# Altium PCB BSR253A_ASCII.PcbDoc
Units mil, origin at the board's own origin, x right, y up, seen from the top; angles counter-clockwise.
Board outline 1000 x 800 mil, 4 copper layers (Top Layer, Signal Layer 1, Signal Layer 2, Bottom Layer), stack 60.6 mil thick; 27 components, 15 nets, 56 pads, 23 vias.
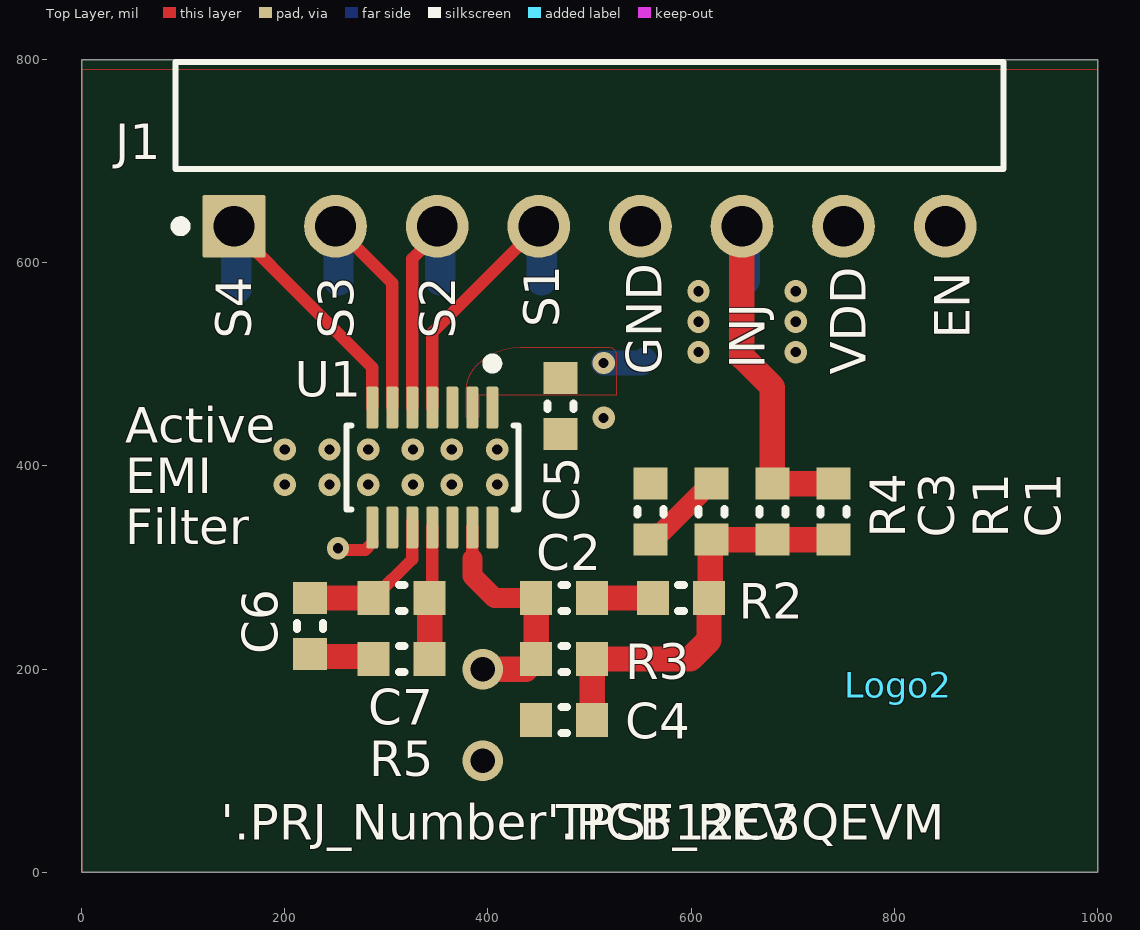
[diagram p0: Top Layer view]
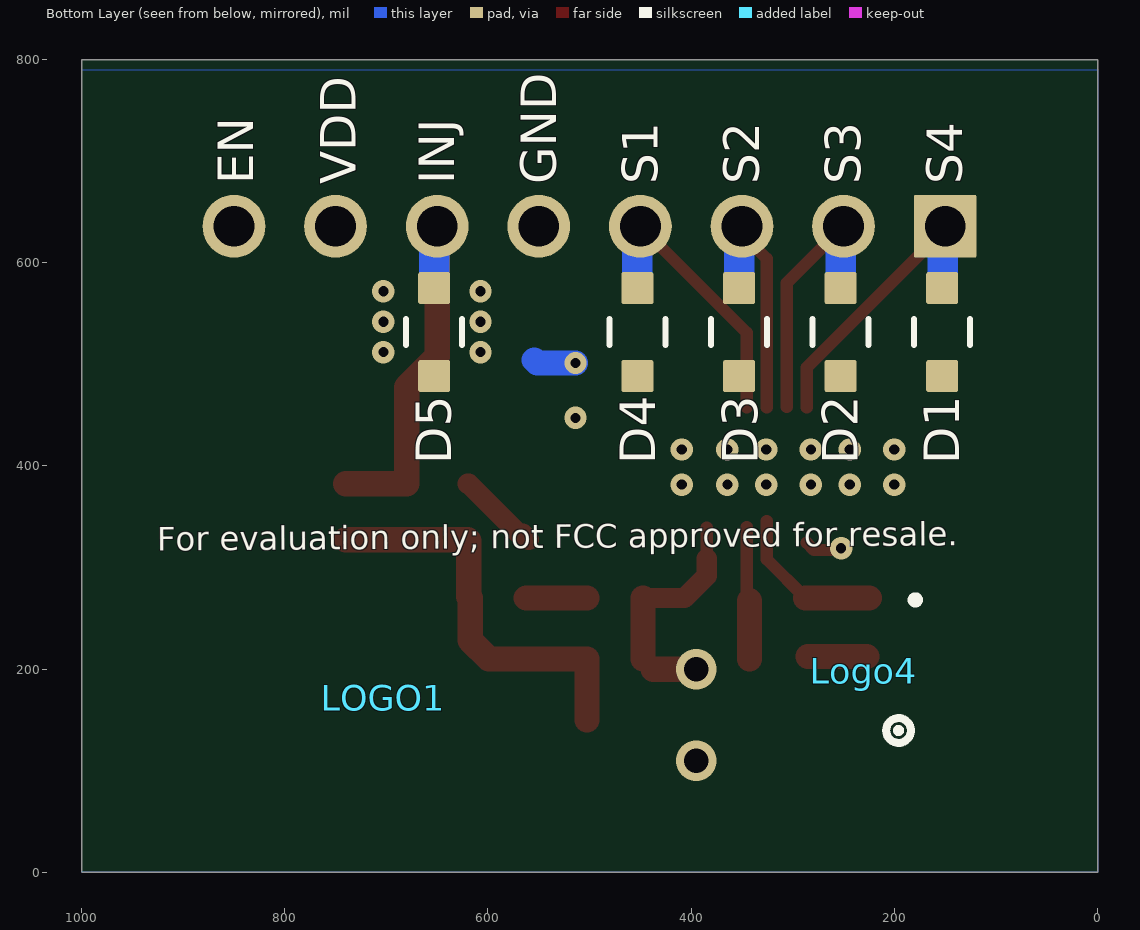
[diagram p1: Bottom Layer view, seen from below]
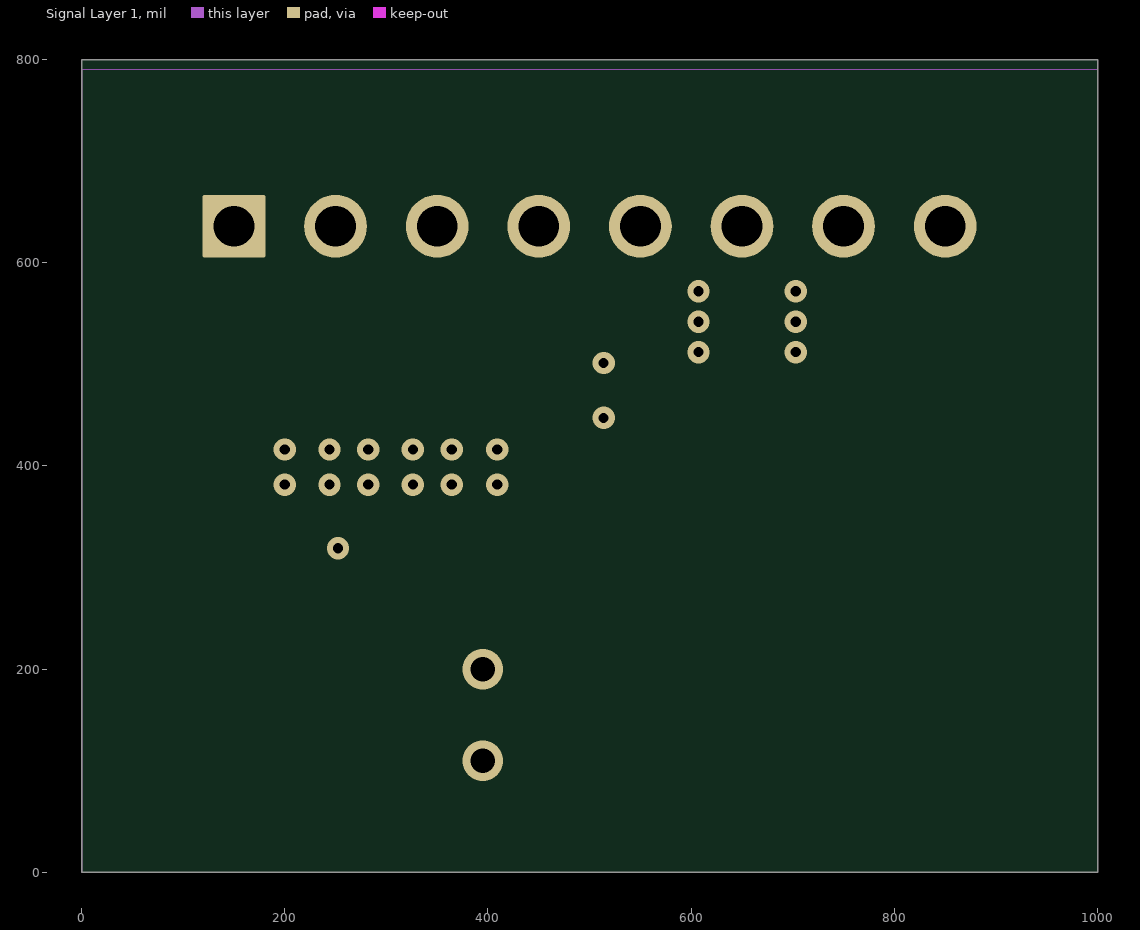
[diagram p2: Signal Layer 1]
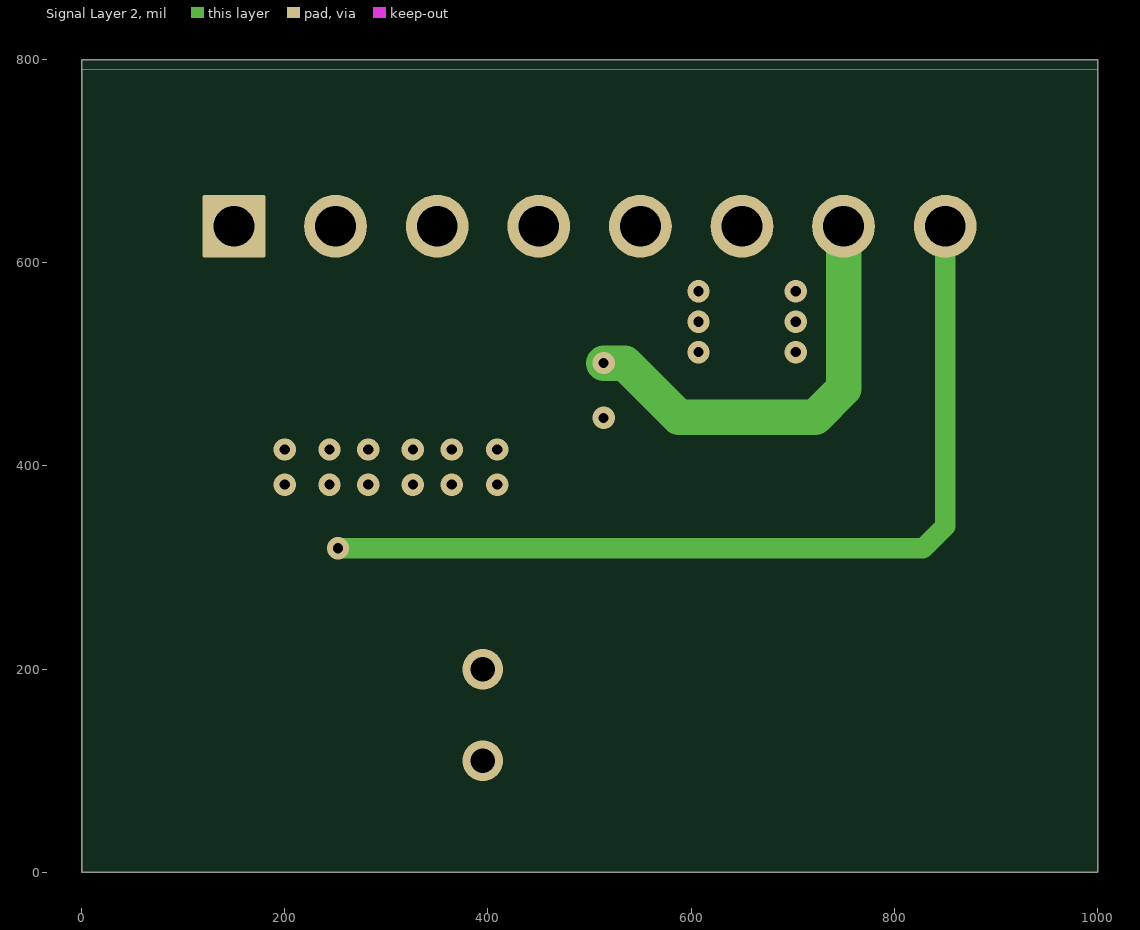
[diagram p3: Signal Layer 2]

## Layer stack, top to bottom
Top Solder: solder mask 0.4, Solder Resist, Dk 3.5
Top Layer: signal copper 1.4
Dielectric 1: prepreg 7, FR-4 High Tg, Dk 4.2
Signal Layer 1: signal copper 1.4
Dielectric 2: core 41, FR-4 High Tg, Dk 4.2
Signal Layer 2: signal copper 1.4
Dielectric 3: prepreg 7, FR-4 High Tg, Dk 4.2
Bottom Layer: signal copper 1.4
Bottom Solder: solder mask 0.4, Solder Resist, Dk 3.5

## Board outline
0,0 1000,0 1000,800 0,800

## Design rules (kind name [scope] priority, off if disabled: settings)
AcuteAngle [All] p0: scope1count=1 scope1_0_kind=Board scope1_0_value=Board scope2count=1 scope2_0_kind=Board scope2_0_value=Board commentlength=0 minimum=4.50000000000000E+0001
AcuteAngle [All] p1: minimum=4.50000000000000E+0001 checktracksonly=FALSE
AssemblyTestPointUsage [All] p0: scope1count=1 scope1_0_kind=Board scope1_0_value=Board scope2count=1 scope2_0_kind=Board scope2_0_value=Board commentlength=0
AssemblyTestPointUsage [All] p1: valid=2
AssemblyTestpoint [All] p0: scope1count=1 scope1_0_kind=Board scope1_0_value=Board scope2count=1 scope2_0_kind=Board scope2_0_value=Board commentlength=0
AssemblyTestpoint [All] p1: testpointundercomponent=FALSE minsize=32 maxsize=100 preferedsize=60 minholesize=0 maxholesize=40 preferedholesize=32 testpointgrid=1 usegrid=TRUE gridtolerance=0.01 allowsidetop=TRUE allowsidebottom=TRUE
BoardOutlineClearance BoardOutlineClearance_MountingHoles [All] p0 off: scope1count=1 scope1_0_kind=Board scope1_0_value=Board scope2count=1 scope2_0_kind=Board scope2_0_value=Board commentlength=86 gap=30 // Protel DXP Scope 1 Expression Was: OnCopper and InComponentClass('Mounting Holes')
BoardOutlineClearance BoardOutlineClearance_Poly [All] p0 off: scope1count=1 scope1_0_kind=Board scope1_0_value=Board scope2count=1 scope2_0_kind=Board scope2_0_value=Board commentlength=58 gap=25 // Protel DXP Scope 1 Expression Was: OnCopper and IsPoly
BoardOutlineClearance [All] p0 off: scope1count=1 scope1_0_kind=Board scope1_0_value=Board scope2count=1 scope2_0_kind=Board scope2_0_value=Board commentlength=172 gap=30 // Protel DXP Scope 1 Expression Was: OnCopper and Not InComponentClass('Logo') and not InComponentClass('FiducialMark') and not InRegion(1000,500,4000,800) and not InPoly
BoardOutlineClearance BoardOutlineClearance_MountingHoles [OnCopper and InComponentClass('Mounting Holes')] p1: gap=30 ignorepadtopadclearanceinfootprint=FALSE
BoardOutlineClearance BoardOutlineClearance_Poly [OnCopper and IsPoly] p2: gap=25 ignorepadtopadclearanceinfootprint=FALSE
BoardOutlineClearance [OnCopper and Not InComponentClass('Logo') and not InComponentClass('FiducialMark') and not InRegion(1000,500,4000,800) and not InPoly] p3: gap=30 ignorepadtopadclearanceinfootprint=FALSE
Clearance Clearance_Poly [All] p0 off: scope1count=1 scope1_0_kind=Board scope1_0_value=Board scope2count=1 scope2_0_kind=Board scope2_0_value=Board commentlength=48 gap=10 // Protel DXP Scope 1 Expression Was: InPolygon
Clearance Clearance_FiducialMark [All] p0 off: scope1count=1 scope1_0_kind=Board scope1_0_value=Board scope2count=1 scope2_0_kind=Board scope2_0_value=Board commentlength=84 gap=0 // Protel DXP Scope 2 Expression Was: IsSMTPin and InComponentClass('FiducialMark')
Clearance [All] p0: scope1count=1 scope1_0_kind=Board scope1_0_value=Board scope2count=1 scope2_0_kind=Board scope2_0_value=Board commentlength=0 gap=6
Clearance Clearance_TopLayer [All] p0: scope1count=1 scope1_0_kind=Layer scope1_0_value=TOP scope2count=1 scope2_0_kind=Layer scope2_0_value=TOP commentlength=0 gap=6
Clearance Clearance_FiducialMark [IsKeepOut and InComponentClass('FiducialMark') vs IsSMTPin and InComponentClass('FiducialMark')] p1: gap=0 ignorepadtopadclearanceinfootprint=TRUE
Clearance Clearance_TopLayer [OnLayer('Top Layer') vs OnLayer('Top Layer')] p2: gap=6 ignorepadtopadclearanceinfootprint=FALSE
Clearance Clearance_Poly [InPolygon] p3: gap=10 ignorepadtopadclearanceinfootprint=FALSE
Clearance [All] p4: gap=6 ignorepadtopadclearanceinfootprint=FALSE
ComponentClearance ComponentClearance_MountingHoles_FiducialMarks [All] p0: scope1count=1 scope1_0_kind=ComponentClass scope1_0_value="Mounting Holes" scope2count=1 scope2_0_kind=ComponentClass scope2_0_value=FiducialMark commentlength=0 gap=50 collisioncheckmode=3
ComponentClearance ComponentClearance_Shunt [All] p0: scope1count=1 scope1_0_kind=ComponentClass scope1_0_value=Header scope2count=1 scope2_0_kind=ComponentClass scope2_0_value=Shunt commentlength=0 gap=0 collisioncheckmode=3
ComponentClearance ComponentClearance_Logo [All] p0: scope1count=1 scope1_0_kind=ComponentClass scope1_0_value=Logo scope2count=1 scope2_0_kind=Board scope2_0_value=Board commentlength=0 gap=0 collisioncheckmode=3
ComponentClearance ComponentClearance_ScrewToNut [All] p0 off: scope1count=1 scope1_0_kind=Board scope1_0_value=Board scope2count=1 scope2_0_kind=Board scope2_0_value=Board commentlength=71 gap=5 collisioncheckmode=3 // Protel DXP Scope 2 Expression Was: (HasFootprint('Keystone_1902C'))
ComponentClearance ComponentClearance_MountingHoles [All] p0: scope1count=1 scope1_0_kind=ComponentClass scope1_0_value="Mounting Holes" scope2count=1 scope2_0_kind=Board scope2_0_value=Board commentlength=0 gap=250 collisioncheckmode=3
ComponentClearance ComponentClearance_SmallPassives [All] p0 off: scope1count=1 scope1_0_kind=Board scope1_0_value=Board scope2count=1 scope2_0_kind=Board scope2_0_value=Board commentlength=508 gap=14.96 collisioncheckmode=3 // Protel DXP Scope 2 Expression Was: HasFootprint('0201*') or HasFootprint('0402*') or HasFootprint('0508') or HasFootprint('0603*') or HasFootprint('0612') or HasFootprint('0805*') or HasFootprint('0815*') or HasFootprint('0830*') or HasFootprint('1206*') or HasFootprint('1210*') or HasFootprint('1808*') or HasFootprint('1812*') or HasFootprint('1825*') or HasFootprint('2010*') or HasFootprint('2220*') or HasFootprint('2225*') or HasFootprint('2512*') or HasFootprint('2728*') or HasFootprint('3518*')
ComponentClearance ComponentClearance_THtoSMT [All] p0 off: scope1count=1 scope1_0_kind=Board scope1_0_value=Board scope2count=1 scope2_0_kind=Board scope2_0_value=Board commentlength=53 gap=19.68 collisioncheckmode=3 // Protel DXP Scope 2 Expression Was: IsSMTComponent
ComponentClearance ComponentClearance_THtoTH [All] p0 off: scope1count=1 scope1_0_kind=Board scope1_0_value=Board scope2count=1 scope2_0_kind=Board scope2_0_value=Board commentlength=54 gap=30 collisioncheckmode=3 // Protel DXP Scope 2 Expression Was: IsThruComponent
ComponentClearance ComponentClearance_MountingHoles_FiducialMarks [InComponentClass('Mounting Holes') vs InComponentClass('FiducialMark')] p1: gap=50 collisioncheckmode=3 verticalgap=10 showdistances=FALSE
ComponentClearance ComponentClearance_Shunt [InComponentClass('Header') vs InComponentClass('Shunt')] p2: gap=0 collisioncheckmode=3 verticalgap=0 showdistances=FALSE
ComponentClearance ComponentClearance_Logo [InComponentClass('Logo')] p3: gap=0 collisioncheckmode=3 verticalgap=0 showdistances=FALSE
ComponentClearance ComponentClearance_ScrewToNut [(HasFootprint('NY PMS 440 0025 PH')) vs (HasFootprint('Keystone_1902C'))] p4: gap=5 collisioncheckmode=3 verticalgap=10 showdistances=FALSE
ComponentClearance ComponentClearance_MountingHoles [InComponentClass('Mounting Holes')] p5: gap=250 collisioncheckmode=3 verticalgap=100000 showdistances=FALSE
ComponentClearance ComponentClearance_SmallPassives [HasFootprint('0201*') or HasFootprint('0402*') or HasFootprint('0508') or HasFootprint('0603*') or HasFootprint('0612') or HasFootprint('0805*') or HasFootprint('0815*') or HasFootprint('0830*') or HasFootprint('1206*') or HasFootprint('1210*') or HasFootprint('1808*') or HasFootprint('1812*') or HasFootprint('1825*') or HasFootprint('2010*') or HasFootprint('2220*') or HasFootprint('2225*') or HasFootprint('2512*') or HasFootprint('2728*') or HasFootprint('3518*') vs HasFootprint('0201*') or HasFootprint('0402*') or HasFootprint('0508') or HasFootprint('0603*') or HasFootprint('0612') or HasFootprint('0805*') or HasFootprint('0815*') or HasFootprint('0830*') or HasFootprint('1206*') or HasFootprint('1210*') or HasFootprint('1808*') or HasFootprint('1812*') or HasFootprint('1825*') or HasFootprint('2010*') or HasFootprint('2220*') or HasFootprint('2225*') or HasFootprint('2512*') or HasFootprint('2728*') or HasFootprint('3518*')] p6: gap=14.96 collisioncheckmode=3 verticalgap=10 showdistances=FALSE
ComponentClearance ComponentClearance_THtoSMT [IsThruComponent vs IsSMTComponent] p7: gap=19.68 collisioncheckmode=3 verticalgap=30 showdistances=FALSE
ComponentClearance ComponentClearance_THtoTH [IsThruComponent vs IsThruComponent] p8: gap=30 collisioncheckmode=3 verticalgap=30 showdistances=FALSE
DiffPairsRouting [All] p0: scope1count=1 scope1_0_kind=Board scope1_0_value=Board scope2count=1 scope2_0_kind=Board scope2_0_value=Board commentlength=0
DiffPairsRouting [All] p1: maxlimit=100 minlimit=10 mostfreqgap=10 toplayer_minwidth=15 toplayer_maxwidth=15 toplayer_prefwidth=15 midlayer1_minwidth=15 midlayer1_maxwidth=15 midlayer1_prefwidth=15 midlayer2_minwidth=15 midlayer2_maxwidth=15 midlayer2_prefwidth=15 bottomlayer_minwidth=15 bottomlayer_maxwidth=15 bottomlayer_prefwidth=15 maxuncoupledlength=1000
FabricationTestPointUsage TestPointUsage [All] p0: scope1count=1 scope1_0_kind=Board scope1_0_value=Board scope2count=1 scope2_0_kind=Board scope2_0_value=Board commentlength=0 valid=2 allowmultiple=FALSE
FabricationTestPointUsage TestPointUsage [All] p1: valid=2 allowmultiple=FALSE
FabricationTestpoint Testpoint [All] p0: scope1count=1 scope1_0_kind=Board scope1_0_value=Board scope2count=1 scope2_0_kind=Board scope2_0_value=Board commentlength=0 side=3 testpointundercomponent=TRUE minsize=32 maxsize=100 preferedsize=60 minholesize=0 maxholesize=40 preferedholesize=32 testpointgrid=1
FabricationTestpoint Testpoint [All] p1: side=3 testpointundercomponent=TRUE minsize=32 maxsize=100 preferedsize=60 minholesize=0 maxholesize=40 preferedholesize=32 testpointgrid=1 allowsidetop=TRUE allowsidebottom=TRUE usegrid=TRUE gridtolerance=0.01
FanoutControl Fanout_LCC [All] p0 off: scope1count=1 scope1_0_kind=Board scope1_0_value=Board scope2count=1 scope2_0_kind=Board scope2_0_value=Board commentlength=69 // Protel DXP Scope 1 Expression Was: IsLCC   Fanout_LCC (Default Rule)
FanoutControl Fanout_BGA [All] p0 off: scope1count=1 scope1_0_kind=Board scope1_0_value=Board scope2count=1 scope2_0_kind=Board scope2_0_value=Board commentlength=69 // Protel DXP Scope 1 Expression Was: IsBGA   Fanout_BGA (Default Rule)
FanoutControl Fanout_SOIC [All] p0 off: scope1count=1 scope1_0_kind=Board scope1_0_value=Board scope2count=1 scope2_0_kind=Board scope2_0_value=Board commentlength=71 // Protel DXP Scope 1 Expression Was: IsSOIC   Fanout_SOIC (Default Rule)
FanoutControl Fanout_Default [All] p0: scope1count=1 scope1_0_kind=Board scope1_0_value=Board scope2count=1 scope2_0_kind=Board scope2_0_value=Board commentlength=30 // Fanout_Default (Default Rule)
FanoutControl Fanout_Small [All] p0 off: scope1count=1 scope1_0_kind=Board scope1_0_value=Board scope2count=1 scope2_0_kind=Board scope2_0_value=Board commentlength=84 // Protel DXP Scope 1 Expression Was: (CompPinCount < 5)   Fanout_Small (Default Rule)
FanoutControl Fanout_LCC [IsLCC] p1: bgadir=Out bgaviamode=Centered fanoutstyle=Auto fanoutdirection=Alternating viagrid=1 // Fanout_LCC (Default Rule)
FanoutControl Fanout_BGA [IsBGA] p2: bgadir=Out bgaviamode=Centered fanoutstyle=Auto fanoutdirection=Alternating viagrid=1 // Fanout_BGA (Default Rule)
FanoutControl Fanout_Default [All] p4: bgadir=Out bgaviamode=Centered fanoutstyle=Auto fanoutdirection=Alternating viagrid=1 // Fanout_Default (Default Rule)
FanoutControl Fanout_Small [(CompPinCount < 5)] p5: bgadir=Out bgaviamode=Centered fanoutstyle=Auto fanoutdirection=OutThenIn viagrid=1 // Fanout_Small (Default Rule)
Height [All] p0: scope1count=1 scope1_0_kind=Board scope1_0_value=Board scope2count=1 scope2_0_kind=Board scope2_0_value=Board commentlength=0
HoleSize [All] p0: scope1count=1 scope1_0_kind=Board scope1_0_value=Board scope2count=1 scope2_0_kind=Board scope2_0_value=Board commentlength=0 absolutevalues=TRUE maxlimit=251 minlimit=7.87 maxpercent=80.000 minpercent=20.000
HoleSize [All] p1: absolutevalues=TRUE maxlimit=251 minlimit=7.87 maxpercent=80.000 minpercent=20.000
HoleToHoleClearance [All] p0: scope1count=1 scope1_0_kind=Board scope1_0_value=Board scope2count=1 scope2_0_kind=Board scope2_0_value=Board commentlength=0
LayerPairs [All] p0: scope1count=1 scope1_0_kind=Board scope1_0_value=Board scope2count=1 scope2_0_kind=Board scope2_0_value=Board commentlength=0 enforce=TRUE
MinimumAnnularRing MinimumAnnularRing_ThermalPadVias [All] p0 off: scope1count=1 scope1_0_kind=Board scope1_0_value=Board scope2count=1 scope2_0_kind=Board scope2_0_value=Board commentlength=63 minimumring=5.91 // Protel DXP Scope 1 Expression Was: IsVia and InAnyComponent
MinimumAnnularRing [All] p0: scope1count=1 scope1_0_kind=Board scope1_0_value=Board scope2count=1 scope2_0_kind=Board scope2_0_value=Board commentlength=0 minimumring=6
MinimumAnnularRing MinimumAnnularRing_ThermalPadVias [IsVia and InAnyComponent] p1: minimumring=5.91
MinimumAnnularRing [All] p2: minimumring=6
MinimumSolderMaskSliver MinimumSolderMaskSliver_Logo [All] p0: scope1count=1 scope1_0_kind=ComponentClass scope1_0_value=Logo scope2count=1 scope2_0_kind=ComponentClass scope2_0_value=Logo commentlength=0
MinimumSolderMaskSliver [All] p0: scope1count=1 scope1_0_kind=Board scope1_0_value=Board scope2count=1 scope2_0_kind=Board scope2_0_value=Board commentlength=0
MinimumSolderMaskSliver MinimumSolderMaskSliver_Logo [InComponentClass('Logo') vs InComponentClass('Logo')] p1: minsoldermaskwidth=0.7
MinimumSolderMaskSliver [All] p2: minsoldermaskwidth=3.94
NetAntennae [All] p0: scope1count=1 scope1_0_kind=Layer scope1_0_value=TOP scope2count=1 scope2_0_kind=Board scope2_0_value=Board commentlength=0
NetAntennae [OnLayer('Top Layer')] p1: netantennaetolerance=0
PasteMaskExpansion [All] p0: scope1count=1 scope1_0_kind=Board scope1_0_value=Board scope2count=1 scope2_0_kind=Board scope2_0_value=Board commentlength=0 expansion=0
PlaneClearance [All] p0: scope1count=1 scope1_0_kind=Board scope1_0_value=Board scope2count=1 scope2_0_kind=Board scope2_0_value=Board commentlength=0 clearance=20
PlaneConnect [All] p0: scope1count=1 scope1_0_kind=Board scope1_0_value=Board scope2count=1 scope2_0_kind=Board scope2_0_value=Board commentlength=0 planeconnectstyle=Direct reliefexpansion=10 reliefentries=4 reliefconductorwidth=10 reliefairgap=10
PlaneConnect [All] p1: planeconnectstyle=Direct reliefexpansion=10 reliefentries=4 reliefconductorwidth=10 reliefairgap=10
PolygonConnect [All] p0: scope1count=1 scope1_0_kind=Board scope1_0_value=Board scope2count=1 scope2_0_kind=Board scope2_0_value=Board commentlength=0 connectstyle=Direct reliefconductorwidth=10 reliefentries=4 polygonreliefangle="90 Angle"
PolygonConnect [All] p1: connectstyle=Direct reliefconductorwidth=10 reliefentries=4 polygonreliefangle="90 Angle" airgapwidth=10
RoutingCorners [All] p0: scope1count=1 scope1_0_kind=Board scope1_0_value=Board scope2count=1 scope2_0_kind=Board scope2_0_value=Board commentlength=0 cornerstyle=45-Degree minsetback=100 maxsetback=100
RoutingLayers [All] p0: scope1count=1 scope1_0_kind=Board scope1_0_value=Board scope2count=1 scope2_0_kind=Board scope2_0_value=Board commentlength=0 top layer=Automatic mid layer 1=Automatic mid layer 2=Automatic bottom layer=Automatic
RoutingPriority [All] p0: scope1count=1 scope1_0_kind=Board scope1_0_value=Board scope2count=1 scope2_0_kind=Board scope2_0_value=Board commentlength=0
RoutingTopology [All] p0: scope1count=1 scope1_0_kind=Board scope1_0_value=Board scope2count=1 scope2_0_kind=Board scope2_0_value=Board commentlength=0 topology=Shortest
RoutingVias ThermalPadVias [All] p0 off: scope1count=1 scope1_0_kind=Board scope1_0_value=Board scope2count=1 scope2_0_kind=Board scope2_0_value=Board commentlength=63 holewidth=7.87 width=19.68 viastyle="Through Hole" minholewidth=7.87 minwidth=19.68 maxholewidth=12.99 maxwidth=23.62 // Protel DXP Scope 1 Expression Was: IsVia and InAnyComponent
RoutingVias [All] p0: scope1count=1 scope1_0_kind=Board scope1_0_value=Board scope2count=1 scope2_0_kind=Board scope2_0_value=Board commentlength=0 holewidth=16 width=34 viastyle="Through Hole" minholewidth=7.87 minwidth=20 maxholewidth=40 maxwidth=65
RoutingVias ThermalPadVias [IsVia and InAnyComponent] p1: holewidth=7.87 width=19.68 viastyle="Through Hole" minholewidth=7.87 minwidth=19.68 maxholewidth=12.99 maxwidth=23.62
RoutingVias [All] p2: holewidth=16 width=34 viastyle="Through Hole" minholewidth=7.87 minwidth=20 maxholewidth=40 maxwidth=65
ShortCircuit [All] p0: scope1count=1 scope1_0_kind=Board scope1_0_value=Board scope2count=1 scope2_0_kind=Board scope2_0_value=Board commentlength=0 allowed=FALSE
SilkToBoardRegionClearance [All] p0 off: scope1count=1 scope1_0_kind=Board scope1_0_value=Board scope2count=1 scope2_0_kind=Board scope2_0_value=Board commentlength=130 // Protel DXP Scope 1 Expression Was: Not ((IsComment or IsDesignator) And (Hide <> 'False')) and not InRegion(1000,500,4000,800)
SilkToBoardRegionClearance [Not ((IsComment or IsDesignator) And (Hide <> 'False')) and not InRegion(1000,500,4000,800)] p1:
SilkToSilkClearance SilkToSilkClearance_Pb-FreeLogo [All] p0 off: scope1count=1 scope1_0_kind=Board scope1_0_value=Board scope2count=1 scope2_0_kind=Board scope2_0_value=Board commentlength=120 // Protel DXP Scope 2 Expression Was: (HasFootprint('Pb-Free_Overlay_Medium') OR HasFootprint('Pb-Free_Overlay_Small'))
SilkToSilkClearance [All] p0: scope1count=1 scope1_0_kind=Board scope1_0_value=Board scope2count=1 scope2_0_kind=Board scope2_0_value=Board commentlength=0
SilkToSilkClearance SilkToSilkClearance_Pb-FreeLogo [(HasFootprint('Pb-Free_Overlay_Medium') OR HasFootprint('Pb-Free_Overlay_Small')) vs (HasFootprint('Pb-Free_Overlay_Medium') OR HasFootprint('Pb-Free_Overlay_Small'))] p1: silktosilkclearance=0
SilkToSilkClearance [All] p2: silktosilkclearance=4
SilkToSolderMaskClearance SilkToComponentPadClearance [All] p0 off: scope1count=1 scope1_0_kind=Board scope1_0_value=Board scope2count=1 scope2_0_kind=Board scope2_0_value=Board commentlength=87 // Protel DXP Scope 1 Expression Was: (IsPad or IsFill or IsRegion) and InAnycomponent
SilkToSolderMaskClearance "Silk to Solder Mask Opening" [All] p0: scope1count=1 scope1_0_kind=Board scope1_0_value=Board scope2count=1 scope2_0_kind=Board scope2_0_value=Board commentlength=0
SilkToSolderMaskClearance SilkToComponentPadClearance [(IsPad or IsFill or IsRegion) and InAnycomponent] p1: minsilkscreentomaskgap=5 clearancetoexposedcopper=TRUE
SilkToSolderMaskClearance "Silk to Solder Mask Opening" [All] p2: minsilkscreentomaskgap=4 clearancetoexposedcopper=FALSE
SolderMaskExpansion [All] p0: scope1count=1 scope1_0_kind=Board scope1_0_value=Board scope2count=1 scope2_0_kind=Board scope2_0_value=Board commentlength=0 expansion=1.97
SolderMaskExpansion [All] p1: expansion=1.97 istentingtop=FALSE
UnRoutedNet [All] p0: scope1count=1 scope1_0_kind=Board scope1_0_value=Board scope2count=1 scope2_0_kind=Board scope2_0_value=Board commentlength=0
UnpouredPolygon [All] p0: scope1count=1 scope1_0_kind=Board scope1_0_value=Board scope2count=1 scope2_0_kind=Board scope2_0_value=Board commentlength=0
Width [All] p0: scope1count=1 scope1_0_kind=Board scope1_0_value=Board scope2count=1 scope2_0_kind=Board scope2_0_value=Board commentlength=0 maxlimit=100 minlimit=10 preferedwidth=10
Width [All] p1: maxlimit=100 minlimit=10 preferedwidth=10 checkconnectedcopper=TRUE
13 further rules are at their usual default settings.

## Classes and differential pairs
component class BSR253A: C1 C2 C3 C4 C5 C6 C7 D1 D2 D3 D4 D5 J1 J4 J5 R1 R2 R3 R4 R5 U1
component class "BSR253A HW": !PCB LOGO1 Logo2 Logo3 Logo4 Logo5 ZZ1 ZZ2 ZZ3 ZZ4
component class AssemblyNote: ZZ1 ZZ2 ZZ3 ZZ4
component class Logo: Logo2

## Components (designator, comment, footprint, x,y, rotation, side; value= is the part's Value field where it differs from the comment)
C1 "C0603C472J5RACTU" 0603L 740,355 r90 top
C2 "GCD188R71H822KA01D" 0603L 475,270 r0 top
C3 "C0603C223K5RACTU" 0603L 620,355 r90 top
C4 "CGA3E2C0G1H100D080AA" 0603L 475,150 r0 top
C5 "CGA3E1X7R1E105K080AC" 0603L 471.39,458.89 r270 top
C6 "C0603X103K5RACTU" 0603L 224.87,242.46 r90 top
C7 "CGA3E2C0G1H100D080AA" 0603L 315,270 r180 top
D1 "STS321050B331" FP-STS321050B331_SOD-323-MFG 152.89,531.81 r270 bottom
D2 "STS321050B331" FP-STS321050B331_SOD-323-MFG 252.89,531.81 r270 bottom
D3 "STS321050B331" FP-STS321050B331_SOD-323-MFG 352.89,531.81 r270 bottom
D4 "STS321050B331" FP-STS321050B331_SOD-323-MFG 452.89,531.81 r270 bottom
D5 "STS321240B301" FP-STS321240B301_SOD-323-MFG 652.89,531.81 r270 bottom
J1 "TSW-108-08-G-S-RA" FP-TSW-108-08-G-S-RA_HDR8-MFG 500,745 r0 top
LOGO1 "CE Mark" CE_Mark_5mm 702.89,171.96 r180 bottom locked (schematic designator Logo1)
Logo2 "Texas Instruments" TI_Symbol_Overlay_Small 803.87,184.51 r0 top locked
Logo3 "FCC disclaimer" FCC_disclaimer -107.92,609.54 r90 bottom
Logo4 "WEEE logo" WEEE_Minimum 230,198 r180 bottom locked
R1 "CRCW0603698RFKEA" 0603L 680,355 r90 top
R2 "CRCW060349R9FKEA" 0603L 590,270 r0 top
R3 "CRCW06031K00FKEA" 0603L 475,210 r0 top
R4 "CRCW0603200RFKEA" 0603L 560,355 r270 top
R5 "CRCW06031K50FKEA" 0603L 315,210 r0 top
U1 "TPSF12C3QDYYRQ1" DYY0014A-MFG 345.22,398.48 r270 top
ZZ1 "These assemblies are ESD sensitive, ESD precautions shall be observed." AssemblyNote -3,1682 r0 top
ZZ2 "These assemblies must be clean and free from flux and all contaminants. Use of no clean flux is not acceptable." AssemblyNote -3,1582 r0 top
ZZ3 "These assemblies must comply with workmanship standards IPC-A-610 Class 2, unless otherwise specified." AssemblyNote -3,1482 r0 top
ZZ4 "Install J2 Receptacle to J1 Header" AssemblyNote -3,1381 r0 top

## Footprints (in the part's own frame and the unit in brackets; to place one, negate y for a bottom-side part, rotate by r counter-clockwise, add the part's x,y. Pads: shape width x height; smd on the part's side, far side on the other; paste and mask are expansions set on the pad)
0603L [mm] "0603 from SM-752 data"
  rect 0.8x0.85 smd: 1(-0.7,0) 2(0.7,0)
  silkscreen extent -0.07,-0.33 0.07,0.33
AssemblyNote [mil] "Assembly Note"
CE_Mark_5mm [mil] "Minimum text height for CE Mark"
DYY0014A-MFG [mm]
  rrect33% 1.05x0.3 smd paste+0 mask+0: 1(-1.5,1.5) 2(-1.5,1) 3(-1.5,0.5) 4(-1.5,0) 5(-1.5,-0.5) 6(-1.5,-1) 7(-1.5,-1.5) 8(1.5,-1.5) 9(1.5,-1) 10(1.5,-0.5) 11(1.5,0) 12(1.5,0.5) 13(1.5,1) 14(1.5,1.5)
  silkscreen extent -2.72,-2.15 1.05,2.15
FCC_disclaimer [mil]
FP-STS321050B331_SOD-323-MFG [mm]
  rrect13% 0.8x0.8 smd paste+0 mask+0: 1(-1.1,0) 2(1.1,0)
  silkscreen extent -0.33,-0.7 0.33,0.7
FP-STS321240B301_SOD-323-MFG [mm]
  rrect13% 0.8x0.8 smd paste+0 mask+0: 1(-1.1,0) 2(1.1,0)
  silkscreen extent -0.33,-0.7 0.33,0.7
FP-TSW-108-08-G-S-RA_HDR8-MFG [mm]
  rrect6% 1.57x1.57 hole 1.02 paste-1000 mask+0: 1(-8.89,-2.77)
  round 1.57 hole 1.02 paste-1000 mask+0: 2(-6.35,-2.77) 3(-3.81,-2.77) 4(-1.27,-2.77) 5(1.27,-2.77) 6(3.81,-2.77) 7(6.35,-2.77) 8(8.89,-2.77)
  silkscreen extent -10.35,-2.89 10.35,1.34
TI_Symbol_Overlay_Small [mil]
WEEE_Minimum [mil] "WEEElie bin"
  silkscreen extent 22,-71 54,74

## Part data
C1: library part CMP-0006942-1, "CAP, CERM, 4700 pF, 50 V, +/- 5%, X7R, 0603"
C2: library part CMP-0007123-4, "CAP, CERM, 8200 pF, 50 V, +/- 10%, X7R, AEC-Q200 Grade 1, 0603"
C3: library part CMP-0006901-4, "CAP, CERM, 0.022 uF, 50 V, +/- 10%, X7R, 0603"
C4 C7: library part CMP-0007069-4, "CAP, CERM, 10 pF, 50 V, +/- 5%, C0G/NP0, AEC-Q200 Grade 1, 0603"
C5: library part CMP-0076705-3, "CAP, CERM, 1 µF, 25 V,+/- 10%, X7R, AEC-Q200 Grade 1, 0603"
C6: library part CMP-0006978-1, "CAP, CERM, 0.01 uF, 50 V, +/- 10%, X7R, 0603"
D1 D2 D3 D4: library part CMP-0092592-1, "18V Clamp 22A (8/20µs) Ipp Tvs Diode Surface Mount SOD-323"
D5: library part CMP-0092593-1, "50V Clamp 8A (8/20µs) Ipp Tvs Diode Surface Mount SOD-323"
J1: library part CMP-0097195-1
LOGO1: library part CMP-0074844-1
Logo2: library part CMP-0074838-1, "Texas Instrument Corporate Signature"
Logo3: library part CMP-0074847-1, "FCC_disclaimer"
Logo4: library part CMP-0074769-1
R1: library part CMP-0022555-5, "RES, 698, 1%, 0.1 W, AEC-Q200 Grade 0, 0603"
R2: library part CMP-0022448-4, "RES, 49.9, 1%, 0.1 W, AEC-Q200 Grade 0, 0603"
R3: library part CMP-0022109-5, "RES, 1.00 k, 1%, 0.1 W, AEC-Q200 Grade 0, 0603"
R4: library part CMP-0022201-5, "RES, 200, 1%, 0.1 W, AEC-Q200 Grade 0, 0603"
R5: library part CMP-0022126-4, "RES, 1.50 k, 1%, 0.1 W, AEC-Q200 Grade 0, 0603"
U1: library part CMP-0092526-6, "Stand Alone Active EMI Filter"
ZZ1: library part CMP-0077236-1
ZZ2: library part CMP-0077237-1
ZZ3 ZZ4: library part CMP-0077238-1

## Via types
v1: diameter 22, hole 10, Top Layer to Bottom Layer, tented both sides, 21 vias
v2: diameter 40, hole 24, Top Layer to Bottom Layer, 2 vias

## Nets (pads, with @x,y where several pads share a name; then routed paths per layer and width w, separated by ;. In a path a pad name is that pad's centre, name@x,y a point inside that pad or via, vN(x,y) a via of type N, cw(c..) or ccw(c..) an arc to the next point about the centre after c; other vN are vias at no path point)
COMP1: C6.2 C7.2 U1.10 | length 154.1
  Top Layer w12: C7.2 325.54,308.1 U1.10 U1.10@325.54,345.75
  Top Layer w25: C6.2@224.88,270.01 C7.2
COMP2: C7.1 R5.2 U1.11 | length 131
  Top Layer w12: C7.1@342.56,267.34 345.22,270 U1.11 U1.11@345.22,339.88
  Top Layer w25: R5.2 C7.1@342.56,267.34
EN: J1.8 U1.8 | length 939.4
  Top Layer w12: v1(252.43,319) 254.06,317.37 279.14,317.37 286.17,324.4 U1.8@286.17,324.76
  Signal Layer 2 w20: v1(252.43,319) 828.21,319 850,340.79 J1.8
IGND: C4.1 C5.2 D1.2 D2.2 D3.2 D4.2 D5.2 J1.5 R4.1 U1.1 U1.3 U1.9 U1.12 U1.14
  other v1: 200.07,381.65 243.98,381.65 282.21,381.65 326.12,381.65 364.36,381.65 409.2,381.65 200.07,416.26 243.98,416.26 282.21,416.26 326.12,416.26 364.36,416.26 409.2,416.26 513.8,447.29 607.29,512 702.89,512 607.29,542 702.89,542 607.29,572 702.89,572
  other v2: 395,110
INJ1: C1.2 D5.1 J1.6 R1.2 | length 373.4
  Top Layer w25: J1.6 649.98,507.63 680,477.61 R1.2 C1.2
  Bottom Layer w30: D5.1@652.89,582.61 J1.6@652.89,630.16
INJECT: C2.1 R3.1 U1.13 | length 236.5
  Top Layer w12: 384.59,308.69 U1.13
  Top Layer w14: R3.1@437.44,200 437.71,200.27 438.69,200.27 447.44,209.02 R3.1
  Top Layer w16: 384.59,308.69 384.75,308.54
  Top Layer w20: 384.75,308.54 384.75,291.89 406.64,270 C2.1
  Top Layer w25: v2(395,200) R3.1@437.44,200 ; R3.1 C2.1
NetC1_1: C1.1 C3.1 C4.2 R1.1 R2.2 R3.2 | length 403.4
  Top Layer w10: C3.1@620,320.15 C3.1@620.5,320.65
  Top Layer w25: C4.2 R3.2 599.15,210 617.56,228.41 R2.2 618.78,271.22 618.78,326.22 C3.1 R1.1 C1.1
NetC2_2: C2.2 R2.1 | length 59.9
  Top Layer w25: C2.2 R2.1
NetC3_2: C3.2 R4.2 | length 82.8
  Top Layer w20: R4.2 565.75,333.19 569.65,333.19 619.02,382.56 C3.2
NetC6_1: C6.1 R5.1 | length 64.6
  Top Layer w12: C6.1 C6.1@227.32,212.45 ; R5.1@284.99,212.45 R5.1
  Top Layer w25: C6.1@227.32,212.45 R5.1@284.99,212.45
SEN1: D4.1 J1.4 U1.4 | length 271.6
  Top Layer w12: U1.4 345.22,531.17 J1.4
  Bottom Layer w10: J1.4@453.05,645.98 J1.4@454.63,644.41
  Bottom Layer w30: D4.1@452.89,582.61 J1.4@452.89,630.16
SEN2: D3.1 J1.3 U1.5 | length 237.3
  Top Layer w12: U1.5 325.54,604.01 350,628.47 J1.3
  Bottom Layer w10: J1.3@353.05,645.98 J1.3@353.94,645.1
  Bottom Layer w30: D3.1@352.89,582.61 J1.3@352.89,630.16
SEN3: D2.1 J1.2 U1.6 | length 248.9
  Top Layer w12: J1.2 305.85,580.09 U1.6@305.85,457.99
  Bottom Layer w10: J1.2@252.88,645.82 J1.2@253.05,645.98
  Bottom Layer w30: D2.1@252.89,582.61 J1.2@252.89,630.16
SEN4: D1.1 J1.1 U1.7 | length 289.9
  Top Layer w12: J1.1@152.89,630.16 221.41,561.63 286.17,496.88 U1.7
  Bottom Layer w30: J1.1 152.14,633.81 152.14,575.87 D1.1
VDD: C5.1 J1.7 U1.2 | length 472.4
  Signal Layer 2 w35: v1(513.8,501.3) 534.7,501.3 588,448 722,448 749.98,475.98 J1.7
  Bottom Layer w10: 554.25,504.25 554.89,503.61
  Bottom Layer w25: v1(513.8,501.3) 551.29,501.3 554.25,504.25

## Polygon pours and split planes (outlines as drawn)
VDD on Top Layer "TOP_LAYER_VDD_P037" (solid, remove dead copper, pour order 37): 526.28,469.79 390.79,469.78 390.79,448 378.71,448 378.71,474.13 cw(c414.23,474.13) 389.11,499.25 cw(c431.79,456.58) 431.79,516.93 518.72,516.93 cw(c518.72,509.37) 526.28,509.36
IGND on Top Layer "TOP_LAYER_IGND_P038" (solid, remove dead copper, pour order 38): 1000,0 1000,790 0,790 0,0
IGND on Signal Layer 1 "SIGNAL_LAYER_1_IGND_P039" (solid, pour order 39): 1000,0 1000,790 0,790 0,0
IGND on Signal Layer 2 "SIGNAL_LAYER_2_IGND_P040" (solid, pour order 40): 1000,0 1000,790 0,790 0,0
IGND on Bottom Layer "BOTTOM_LAYER_IGND_P041" (solid, pour order 41): 1000,0 1000,790 0,790 0,0

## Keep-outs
Keep-Out Layer:
  text ".Layer_Name" at -1132.57,-2670.95 h60

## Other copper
Top Layer:
  text ".Layer_Name" at -1132.57,-2670.95 h60
Signal Layer 1:
  text ".Layer_Name" at -1170,-2678 h60
Signal Layer 2:
  text ".Layer_Name" at -1166,-2678 h60
Bottom Layer:
  text ".Layer_Name" at -1132.57,-2670.95 h60

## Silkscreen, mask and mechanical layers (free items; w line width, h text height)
Top Overlay:
  text "S1" at 470,536.66 h35 r90
  text "S4" at 167,525 h35 r90
  text "S3" at 268,525 h35 r90
  text "S2" at 368,525 h35 r90
  text "EN" at 874.15,525 h35 r90
  text "INJ" at 672.39,495.84 h35 r90
  text "GND" at 571.06,490.01 h35 r90
  text "VDD" at 772.01,490.01 h35 r90
  text "Active" at 43,423 h35
  text "EMI" at 43,373 h35
  text "Filter" at 43,323 h35
  text "'.PRJ_Number'.PCB_REV" at 137,32 h35
  text "TPSF12C3QEVM" at 467,32 h35
  text ".Layer_Name" at -1132.57,-2670.95 h60
Bottom Overlay:
  text "S4" at 133,677.44 h35 r270
  text "S3" at 233,677.44 h35 r270
  text "S2" at 333,677.44 h35 r270
  text "S1" at 433,677.44 h35 r270
  text "GND" at 533,677.44 h35 r270
  text "INJ" at 633,677.44 h35 r270
  text "VDD" at 730,677.44 h35 r270
  text "EN" at 831,677.44 h35 r270
  text ".Layer_Name" at -1132.57,-2670.95 h60
Top Paste:
  text ".Layer_Name" at -1132.57,-2670.95 h60
Bottom Paste:
  text ".Layer_Name" at -1132.57,-2670.95 h60
Top Solder:
  text ".Layer_Name" at -1132.57,-2670.95 h60
  text ".Layer_Name" at -1132.57,-2670.95 h60
Bottom Solder:
  text ".Layer_Name" at -1132.57,-2670.95 h60
Drill Guide:
  text ".Layer_Name" at -1132.57,-2670.95 h60
M1 Board Outline:
  the board outline again, w10
  text ".Layer_Name" at -1132.57,-2670.95 h60
M2 Board Dimensions:
  rectangle: -1709.57,-2087.46 -1584.57,-1962.46
  rectangle: -1584.57,-2212.46 -1209.57,-2087.46
  lines w7: -1709.57,-2087.46 -709.57,-2087.46 ; -1584.57,-2212.46 -1584.57,-1962.46 ; -1459.57,-2212.46 -1459.57,-1962.46 ; -1209.57,-2212.46 -1209.57,-1962.46 ; -959.57,-2212.46 -959.57,-1962.46 ; -1709.57,-2212.46 -709.57,-2212.46 -709.57,-1962.46 -1709.57,-1962.46 -1709.57,-2212.46
  text ".Layer_Name" at -1132.57,-2670.95 h60
M3 3D STEP Top:
  text ".Layer_Name" at -1132.57,-2670.95 h60
M4 3D STEP Bottom:
  text ".Layer_Name" at -1132.57,-2670.95 h60
M5 Assembly Top:
  lines w10: -2001.57,-2742.62 4598.43,-2742.62 ; -2001.57,-2539.29 4600.43,-2539.29 ; -2001.57,-2335.96 -2001.57,-2945.96 2003.43,-2945.96 4600.43,-2945.96 4600.43,-2335.96 -2001.07,-2335.96 -2001.07,-2945.96 -425.57,-2945.96 ; 463.43,-2945.96 463.43,-2335.96 ; 1730.43,-2539.29 1730.43,-2335.96 ; 2570.43,-2539.29 2570.43,-2335.96 ; 3192.43,-2952.46 3192.43,-2749.62
  text "COMPONENTS MARKED 'DNP' SHOULD NOT BE POPULATED." at -556.07,-2130.96 h60
  text "ASSEMBLY VARIANT:" at -556.57,-2246.46 h60
  text ".VariantName" at 479.43,-2246.46 h60
  text "PCB VIEWED FROM TOP SIDE" at -1938.07,-2468.12 h60
  text "BOARD #:" at 538.43,-2468.12 h60
  text ".PRJ_Number" at 1083.93,-2468.12 h60
  text "REV:" at 1928.43,-2468.12 h60
  text ".PCB_Rev" at 2219.93,-2468.12 h60
  text "SVN REV:" at 2766.43,-2468.12 h60
  text ".VersionControl_RevNumber" at 3272.43,-2468.12 h60
  text "TID #:" at 538.43,-2671.46 h60
  text ".TID" at 1083.93,-2671.46 h60
  text "PLOT NAME =" at -1938.07,-2876.79 h60
  text ".plot_File_Name" at -1132.57,-2876.79 h60
  text "GENERATED    :" at 540.43,-2876.79 h60
  text ".Print_Date" at 1409.93,-2876.79 h60
  text ".Print_Time" at 2138.93,-2876.79 h60
  text "TEXAS INSTRUMENTS" at 3403.43,-2876.79 h60
M6 Assembly Bottom:
  lines w10: -2002.07,-2539.79 4599.93,-2539.79 ; -2000.07,-2743.12 4599.93,-2743.12 ; -594.07,-2952.96 -594.07,-2750.12 ; 27.93,-2539.79 27.93,-2336.46 ; 867.93,-2539.79 867.93,-2336.46 ; 2134.93,-2946.46 2134.93,-2336.46 ; 3023.93,-2946.46 4599.43,-2946.46 4599.43,-2336.46 -2002.07,-2336.46 -2002.07,-2946.46 594.93,-2946.46 4599.93,-2946.46 4599.93,-2336.46
  text "COMPONENTS MARKED 'DNP' SHOULD NOT BE POPULATED." at 5140.82,-2127.42 h60
  text ".VariantName" at 4104.33,-2246.46 h60
  text "ASSEMBLY VARIANT:" at 5143.33,-2246.46 h60
  text ".VersionControl_RevNumber" at -674.07,-2468.62 h60
  text "SVN REV:" at -168.07,-2468.62 h60
  text ".PCB_Rev" at 378.43,-2468.62 h60
  text "REV:" at 669.93,-2468.62 h60
  text ".PRJ_Number" at 1514.43,-2468.62 h60
  text "BOARD #:" at 2059.93,-2468.62 h60
  text "PCB VIEWED FROM BOTTOM SIDE" at 4536.43,-2468.62 h60
  text ".TID" at 1514.43,-2671.96 h60
  text "TID #:" at 2059.93,-2671.96 h60
  text "TEXAS INSTRUMENTS" at -805.07,-2877.29 h60
  text ".Print_Time" at 459.43,-2877.29 h60
  text ".Print_Date" at 1188.43,-2877.29 h60
  text "GENERATED    :" at 2057.93,-2877.29 h60
  text ".plot_File_Name" at 3730.93,-2877.29 h60
  text "PLOT NAME =" at 4536.43,-2877.29 h60
M9 Title Sheet:
  lines w10: -2201.07,-770.96 -2001.07,-770.96 ; -2201.07,1604.04 -2001.07,1604.04 ; -2201.07,3979.04 -2001.07,3979.04 ; 298.93,-3145.96 298.93,-2945.96 ; 298.93,6154.04 298.93,6354.04 ; 2798.93,-3145.96 2798.93,-2945.96 ; 2798.93,6154.04 2798.93,6354.04 ; 4611.43,-2945.96 4611.43,-2335.96 9593.93,-2335.96 ; 5298.93,-3145.96 5298.93,-2945.96 ; 5298.93,6154.04 5298.93,6354.04 ; 7798.93,-3145.96 7798.93,-2945.96 ; 7798.93,6154.04 7798.93,6354.04 ; 9593.93,-2945.96 9593.93,-2335.96 ; 9593.93,-2635.96 12593.93,-2635.96 ; 9593.93,-2035.96 12593.93,-2035.96 ; 9594.93,-1441.96 12594.93,-1441.96 ; 10298.93,-3145.96 10298.93,-2945.96 ; 10298.93,6154.04 10298.93,6354.04 ; 11098.93,-2935.96 11098.93,-2335.96 ; 12593.93,-2335.96 9593.93,-2335.96 ; 12593.93,-1735.96 9593.93,-1735.96 ; 12598.93,-1745.96 12598.93,-2945.96 ; 12598.93,-941.46 9594.93,-941.46 9593.93,-941.46 9593.93,-1441.96 9593.93,-1735.96 ; 12598.93,-770.96 12798.93,-770.96 ; 12598.93,1604.04 12798.93,1604.04 ; 12598.93,3979.04 12798.93,3979.04 ; 9593.93,-2335.96 9593.93,-1735.96 ; 12598.93,-2945.96 12598.93,6154.04 -2001.07,6154.04 -2001.07,-2945.96 12598.93,-2945.96 ; -2201.07,-3145.96 -2201.07,6354.04 12798.93,6354.04 12798.93,-3145.96 -2201.07,-3145.96
  text "1" at -969.74,6224.04 h70
  text "2" at 1525.93,6224.04 h70
  text "3" at 4015.27,6224.04 h70
  text "4" at 6521.94,6224.04 h70
  text "5" at 9020.93,6224.04 h70
  text "6" at 11525.93,6224.04 h70
  text "A" at -2126.07,5081.04 h70
  text "A" at 12673.93,5081.04 h70
  text "B" at -2126.07,2701.04 h70
  text "B" at 12673.93,2701.04 h70
  text "C" at -2126.07,326.04 h70
  text "C" at 12673.93,326.04 h70
  text "PROJECT TITLE:" at 9633.93,-1534.96 h45
  text ".PRJ_Title" at 9683.93,-1668.28 h70
  text "DESIGNED FOR:" at 9633.93,-1835.96 h45
  text ".PRJ_Customer" at 9683.93,-1975.96 h70
  text "D" at -2126.07,-2043.96 h70
  text "D" at 12673.93,-2043.96 h70
  text "FILE NAME:" at 9633.93,-2135.96 h45
  text ".PCB_File_Name_No_Path" at 9683.93,-2255.96 h70
  text "Texas Instruments (TI) and/or its licensors do not warrant the accuracy or completeness of this specification" at 4664.43,-2417.8 h45
  text "ENGINEER:" at 9633.93,-2425.96 h45
  text "LAYOUT BY:" at 11138.93,-2425.96 h45
  text "or any information contained therein. TI and/or its licensors do not warrant that this design will meet" at 4619.44,-2530.46 h45
  text ".PRJ_Engineer" at 9683.93,-2580.95 h70
  text "Tony Jacobs" at 11189.43,-2580.95 h70
  text "the specifications, will be suitable for your application or fit for any particular purpose, or will operate in" at 4619.44,-2643.13 h45
  text ".Layer_Name" at -1132.57,-2670.95 h60
  text "ALTIUM DESIGNER VERSION:" at 11138.93,-2735.96 h45
  text "an implementation. TI and/or its licensors do not warrant that the design is production worthy. You should" at 4619.44,-2755.79 h45
  text "completely validate and test your design implementation to confirm the system functionality for your application." at 4664.43,-2868.46 h45
  text ".print_Scale" at 9683.93,-2869.28 h70
  text ".Application_BuildNumber" at 11189.43,-2869.28 h70
  text "1" at -969.74,-3075.96 h70
  text "2" at 1525.93,-3075.96 h70
  text "3" at 4015.27,-3075.96 h70
  text "4" at 6521.94,-3075.96 h70
  text "5" at 9020.93,-3075.96 h70
  text "6" at 11525.93,-3075.96 h70
M10 Fab Notes:
  drawing of 189 lines, arcs and shapes, not listed
  text "DESIGN INFORMATION" at 10672.44,4543.72 h60
  text "MIN. TRACK WIDTH:" at 10027.88,4411.59 h60
  text "10" at 11124.13,4411.59 h60
  text "MIL" at 11278.88,4411.59 h60
  text "6" at 11161,4290 h60
  text "MIN. CLEARANCE:" at 10027.88,4287.47 h60
  text "MIL" at 11278.88,4287.47 h60
  text "MIN. VIA PAD SIZE:" at 10027.88,4163.34 h60
  text "20" at 11094.14,4163.34 h60
  text "MIL" at 11278.88,4163.34 h60
  text "0.05mm (2MIL)" at 10722.88,4033.44 h60
  text "MINIMUM ANNULAR RING" at 9698.65,4025.22 h60
  text "EXTERNAL" at 11430.88,4025.22 h60
  text "PER" at 9898.65,3915.09 h60
  text "IPC-D-275 CLASS 2 LEVEL C" at 10118.65,3915.09 h60
  text "MIL, HOLES" at 11606.88,3814.61 h60
  text "+/-" at 11214.43,3806.03 h60
  text "+/-" at 12068.43,3806.03 h60
  text "REGISTRATION TOLERANCES:" at 9698.65,3804.96 h60
  text "METAL" at 10898.43,3804.96 h60
  text "5" at 11474.63,3804.96 h60
  text "3" at 12307.63,3804.96 h60
  text "MIL" at 12423.88,3804.96 h60
  text "HOLE SIZE TOLERANCE (UNLESS OTHERWISE SPECIFIED):" at 9698.65,3706.65 h60
  text "+/-" at 12068.43,3703.77 h60
  text "3" at 12307.63,3702.71 h60
  text "MIL" at 12423.88,3702.71 h60
  text "MATERIAL:" at 9623.88,3565.06 h60
  text "FR-4 High Tg" at 10610.33,3436.54 h60
  text "X" at 10465.89,3428.55 h60
  text "FR-408" at 10044.89,3424.03 h60
  text "OTHER" at 11532.88,3424.03 h60
  text "62 MIL (1.6mm) +/-10%" at 10364.99,3281 h60
  text "X" at 10243,3278 h60
  text "THICKNESS:" at 9698.65,3272.78 h60
  text "OTHER" at 11649.89,3272.78 h60
  text "TOLERANCE:" at 9698.65,3134.47 h60
  text "X" at 10546.89,3134.47 h60
  text "ANSI IPC-6012 TYPE 3 CLASS 2" at 10724.9,3134.47 h60
  text "OTHER +/-" at 10724.88,2990.28 h60
  text "BOW & TWIST:" at 9698.65,2845.09 h60
  text "X" at 10546.89,2845.09 h60
  text "ANSI IPC-6012 TYPE 3 CLASS 2" at 10724.9,2845.09 h60
  text "OTHER +/-" at 10724.88,2698.39 h60
  text "DRILLING:" at 9623.88,2567.77 h60
  text "NC_DRILL FILES" at 11384.88,2462.58 h60
  text "REFERENCE:" at 9698.65,2458.65 h60
  text "X" at 10355.89,2458.55 h60
  text "AS SHOWN" at 10533.88,2458.65 h60
  text "X" at 11256.89,2458.65 h60
  text "OTHER" at 11682.88,2316.39 h60
  text "PTH COPPER THICKNESS:" at 9698.33,2312.87 h60
  text "X" at 10837.57,2312.87 h60
  text "20-30 um" at 10965.56,2312.87 h60
  text "BOARD FINISH:" at 9623.88,2165.27 h60
  text "SILKSCREEN:" at 9779.11,2055.14 h60
  text "X" at 10736.89,2055.14 h60
  text "TOP" at 10853.88,2055.14 h60
  text "X" at 11246.89,2055.14 h60
  text "BOTTOM" at 11364.88,2055.14 h60
  text "SILKSCREEN COLOR:" at 9779.11,1899.95 h60
  text "X" at 10735.89,1899.95 h60
  text "WHITE" at 10853.88,1899.95 h60
  text "OTHER" at 11364.88,1899.95 h60
  text "X" at 10866.89,1756.51 h60
  text "GREEN" at 10984.88,1756.51 h60
  text "OTHER" at 11602.88,1756.51 h60
  text "SOLDER RESIST COLOR:" at 9779.11,1749.64 h60
  text "X" at 10866.89,1602.25 h60
  text "MATTE" at 10984.88,1602.25 h60
  text "SEMI-GLOSS" at 11602.42,1601.62 h60
  text "IMMERSION GOLD (ENIG)" at 10684.88,1429.48 h60
  text "ENEPIG" at 12022.43,1422.26 h60
  text "SURFACE FINISH:" at 9623.88,1421.26 h60
  text "X" at 10506.89,1421.26 h60
  text "IMM. TIN/SILVER OR EQUIV" at 9953.43,1283.95 h60
  text "OTHER" at 11384.88,1280.01 h60
  text "ARRAY/PANEL:" at 9623.88,1124.63 h60
  text "CUT AND TRIM PER M1 BOARD OUTLINE" at 10684.89,1116.41 h60
  text "N.C. ROUTE" at 10684.88,980.44 h60
  text "X" at 11372.89,980.44 h60
  text "V. SCORE" at 11550.88,980.44 h60
  text "CERTIFICATION:" at 9623.88,851.32 h60
  text "MATERIALS AND WORKMANSHIP FOR ALL PCBS" at 10348.88,851.32 h60
  text "TO MEET OR EXCEED THE REQUIREMENTS OF:" at 10348.88,757.25 h60
  text "X" at 9986.39,628.62 h60
  text "ANSI IPC-A-600F CLASS ->" at 10114.39,628.62 h60
  text "X" at 11762.39,628.62 h60
  text "2" at 11872.39,628.62 h60
  text "1" at 11557.39,627.13 h60
  text "3" at 12226.39,627.13 h60
  text "X" at 10798.39,480.94 h60
  text "RoHS" at 10926.39,480.94 h60
  text "OTHER" at 11570.79,480.94 h60
  text "PER ORDER" at 11967.85,480.94 h60
  text "ALL BOARDS MUST MEET OR EXCEED UL94-V0 REQUIREMENTS." at 9651.43,327.11 h60
  text "PCB MUST BEAR THE UL94V-0 UL REGISTERED MATERIAL ID NUMBER" at 9651.43,211.05 h60
  text "ADDITIONAL REQUIREMENTS:" at 9623.88,41.62 h60
  text "MICROSECTION:" at 9698.65,-65.5 h60
  text "YES" at 10604.39,-65.5 h60
  text "REQUIRED" at 11465.88,-209.84 h60
  text "BARE BOARD ELEC. TEST:" at 9698.65,-212.69 h60
  text "NONE" at 11004.39,-212.69 h60
  text "X" at 11347.89,-212.69 h60
  text "PER ORDER" at 12057.88,-212.69 h60
  text "XX MIL VIAS REQUIRE NON-CONDUCTIVE FILL AND PLANARIZE" at 9866.8,-417.64 h59
  text "XX MIL VIAS REQUIRE CONDUCTIVE FILL AND PLANARIZE" at 9874.8,-521.61 h60
  text "OUTER XX MIL TRACES REQUIRE 50 OHM SINGLE-ENDED IMPEDANCE" at 9873.82,-685 h58
  text "LAYER 2 & 3 (INNER LAYERS) XX MIL WIDE, XX MIL SPACE / TRACES REQUIRE 100 OHM DIFFERENTIAL IMPEDANCE" at 9865.82,-920.71 h60
  text ".Layer_Name" at -1132.57,-2670.95 h60
M11 Gerber Information:
  lines w10: -2001.57,-2742.62 4598.43,-2742.62 ; -2001.57,-2539.29 4600.43,-2539.29 ; -2001.57,-2335.96 -2001.57,-2945.96 2003.43,-2945.96 4600.43,-2945.96 4600.43,-2335.96 -2001.07,-2335.96 -2001.07,-2945.96 -425.57,-2945.96 ; 463.43,-2945.96 463.43,-2335.96 ; 1730.43,-2539.29 1730.43,-2335.96 ; 2570.43,-2539.29 2570.43,-2335.96 ; 3192.43,-2952.46 3192.43,-2749.62
  text "ALL ARTWORK VIEWED FROM TOP SIDE" at -1938.07,-2468.12 h60
  text "BOARD #:" at 538.43,-2468.12 h60
  text ".PRJ_Number" at 1083.93,-2468.12 h60
  text "REV:" at 1928.43,-2468.12 h60
  text ".PCB_Rev" at 2219.93,-2468.12 h60
  text "SVN REV:" at 2766.43,-2468.12 h60
  text ".VersionControl_RevNumber" at 3272.43,-2468.12 h60
  text "LAYER NAME =" at -1938.07,-2670.95 h60
  text "TID #:" at 538.43,-2671.46 h60
  text ".TID" at 1083.93,-2671.46 h60
  text "PLOT NAME =" at -1938.07,-2876.79 h60
  text ".plot_File_Name" at -1132.57,-2876.79 h60
  text "GENERATED    :" at 540.43,-2876.79 h60
  text ".Print_Date" at 1409.93,-2876.79 h60
  text ".Print_Time" at 2138.93,-2876.79 h60
  text "TEXAS INSTRUMENTS" at 3403.43,-2876.79 h60
M12 Stackup:
  drawing of 295 lines, arcs and shapes, not listed
  text "LAYER STACK UP: REFERENCE ONLY" at 5136.89,4911.3 h90
  text "ALL LAYERS: 1 ounce Cu (1.4 mils)" at 5606.89,4721.3 h70
  text "Layer" at 4230.64,4446.01 h60
  text "Name" at 4640.56,4446.01 h60
  text "Material" at 5580.3,4446.01 h60
  text "Thickness" at 6440.06,4446.01 h60
  text "Constant" at 7089.9,4446.01 h60
  text "Board Layer Stack" at 7659.76,4446.01 h60
  text "Top Overlay" at 4640.56,4326.01 h60
  text "Top Solder" at 4640.56,4206.01 h60
  text "Solder Resist" at 5580.3,4206.01 h60
  text "0.40mil" at 6440.06,4206.01 h60
  text "3.5" at 7089.9,4206.01 h60
  text "1" at 4230.64,4086.01 h60
  text "Top Layer" at 4640.56,4086.01 h60
  text "1.40mil" at 6440.06,4086.01 h60
  text "Dielectric 1" at 4640.56,3966.01 h60
  text "FR-4 High Tg" at 5580.3,3966.01 h60
  text "7.00mil" at 6440.06,3966.01 h60
  text "4.2" at 7089.9,3966.01 h60
  text "2" at 4230.64,3846.01 h60
  text "Signal Layer 1" at 4640.56,3846.01 h60
  text "1.40mil" at 6440.06,3846.01 h60
  text "Dielectric 2" at 4640.56,3726.01 h60
  text "FR-4 High Tg" at 5580.3,3726.01 h60
  text "41.00mil" at 6440.06,3726.01 h60
  text "4.2" at 7089.9,3726.01 h60
  text "3" at 4230.64,3606.01 h60
  text "Signal Layer 2" at 4640.56,3606.01 h60
  text "1.40mil" at 6440.06,3606.01 h60
  text "Dielectric 3" at 4640.56,3486.01 h60
  text "FR-4 High Tg" at 5580.3,3486.01 h60
  text "7.00mil" at 6440.06,3486.01 h60
  text "4.2" at 7089.9,3486.01 h60
  text "4" at 4230.64,3366.01 h60
  text "Bottom Layer" at 4640.56,3366.01 h60
  text "1.40mil" at 6440.06,3366.01 h60
  text "Bottom Solder" at 4640.56,3246.01 h60
  text "Solder Resist" at 5580.3,3246.01 h60
  text "0.40mil" at 6440.06,3246.01 h60
  text "3.5" at 7089.9,3246.01 h60
  text "Bottom Overlay" at 4640.56,3126.01 h60
  text "Total board thickness:" at 4230.64,3006.01 h60
  text "61.40mil" at 6440.06,3006.01 h60
  text ".Layer_Name" at -1132.57,-2670.95 h60
M13 Component Bodies Top:
  text ".Layer_Name" at -1132.57,-2670.95 h60
M14 Component Bodies Bottom:
  text ".Layer_Name" at -1132.57,-2670.95 h60
M15 Courtyards Top:
  text ".Layer_Name" at -1132.57,-2670.95 h60
M16 Courtyards Bottom:
  text ".Layer_Name" at -1132.57,-2670.95 h60
Drill Drawing:
  lines w10: 5525.72,2357.48 5580.98,2357.48 5580.98,2412.73 5525.72,2412.73 5525.72,2357.48 ; 5525.72,2495.61 5539.54,2495.61 5553.35,2481.8 5567.16,2495.61 5580.98,2495.61 5567.16,2509.42 5580.98,2523.24 5567.16,2523.24 5553.35,2537.05 5539.54,2523.24 5525.72,2523.24 5539.54,2509.42 5525.72,2495.61 ; 5525.72,2661.37 5580.98,2661.37 5553.35,2606.12 5525.72,2661.37
  lines w12: 5475.63,2320.18 8707.12,2320.18 ; 5475.63,2693.14 8707.12,2693.14 ; 5813.5,2195.86 5813.5,2817.46 ; 6145.5,2195.86 6145.5,2817.46 ; 6782.06,2195.86 6782.06,2817.46 ; 7041.2,2195.86 7041.2,2817.46 ; 7416.36,2195.86 7416.36,2817.46 ; 8140.69,2195.86 8140.69,2817.46 ; 5475.63,2195.86 8707.12,2195.86 8707.12,2817.46 5475.63,2817.46 5475.63,2195.86
  text "Symbol" at 5550.23,2730.44 h72
  text "Quantity" at 5850.79,2730.44 h72
  text "Finished Hole Size" at 6182.79,2730.44 h72
  text "Plated" at 6819.36,2730.44 h72
  text "Hole Type" at 7078.5,2730.44 h72
  text "Drill Layer Pair" at 7453.65,2730.44 h72
  text "Hole Tolerance" at 8177.98,2730.44 h72
  text "21" at 5850.79,2606.12 h60
  text "10.00mil (0.254mm)" at 6182.79,2606.12 h60
  text "PTH" at 6819.36,2606.12 h60
  text "Round" at 7078.5,2606.12 h60
  text "Top Layer - Bottom Layer" at 7453.65,2606.12 h60
  text "2" at 5850.79,2481.8 h60
  text "24.00mil (0.610mm)" at 6182.79,2481.8 h60
  text "PTH" at 6819.36,2481.8 h60
  text "Round" at 7078.5,2481.8 h60
  text "Top Layer - Bottom Layer" at 7453.65,2481.8 h60
  text "8" at 5850.79,2357.48 h60
  text "40.16mil (1.020mm)" at 6182.79,2357.48 h60
  text "PTH" at 6819.36,2357.48 h60
  text "Round" at 7078.5,2357.48 h60
  text "Top Layer - Bottom Layer" at 7453.65,2357.48 h60
  text "31 Total" at 5850.79,2233.16 h60
  text ".Layer_Name" at -1132.57,-2670.95 h60
M17 Embedded Cavity:
  text ".Layer_Name" at -1132.57,-2670.95 h60
M18 Embedded Assembly:
  text ".Layer_Name" at -1132.57,-2670.95 h60
M19 Embedded Keepout:
  text ".Layer_Name" at -1132.57,-2670.95 h60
